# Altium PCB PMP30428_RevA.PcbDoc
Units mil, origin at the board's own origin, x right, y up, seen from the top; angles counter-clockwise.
Board outline 3031.5 x 2874.02 mil, 2 copper layers (Top Layer, Bottom Layer), stack 62 mil thick; 56 components, 35 nets, 134 pads, 10 vias.
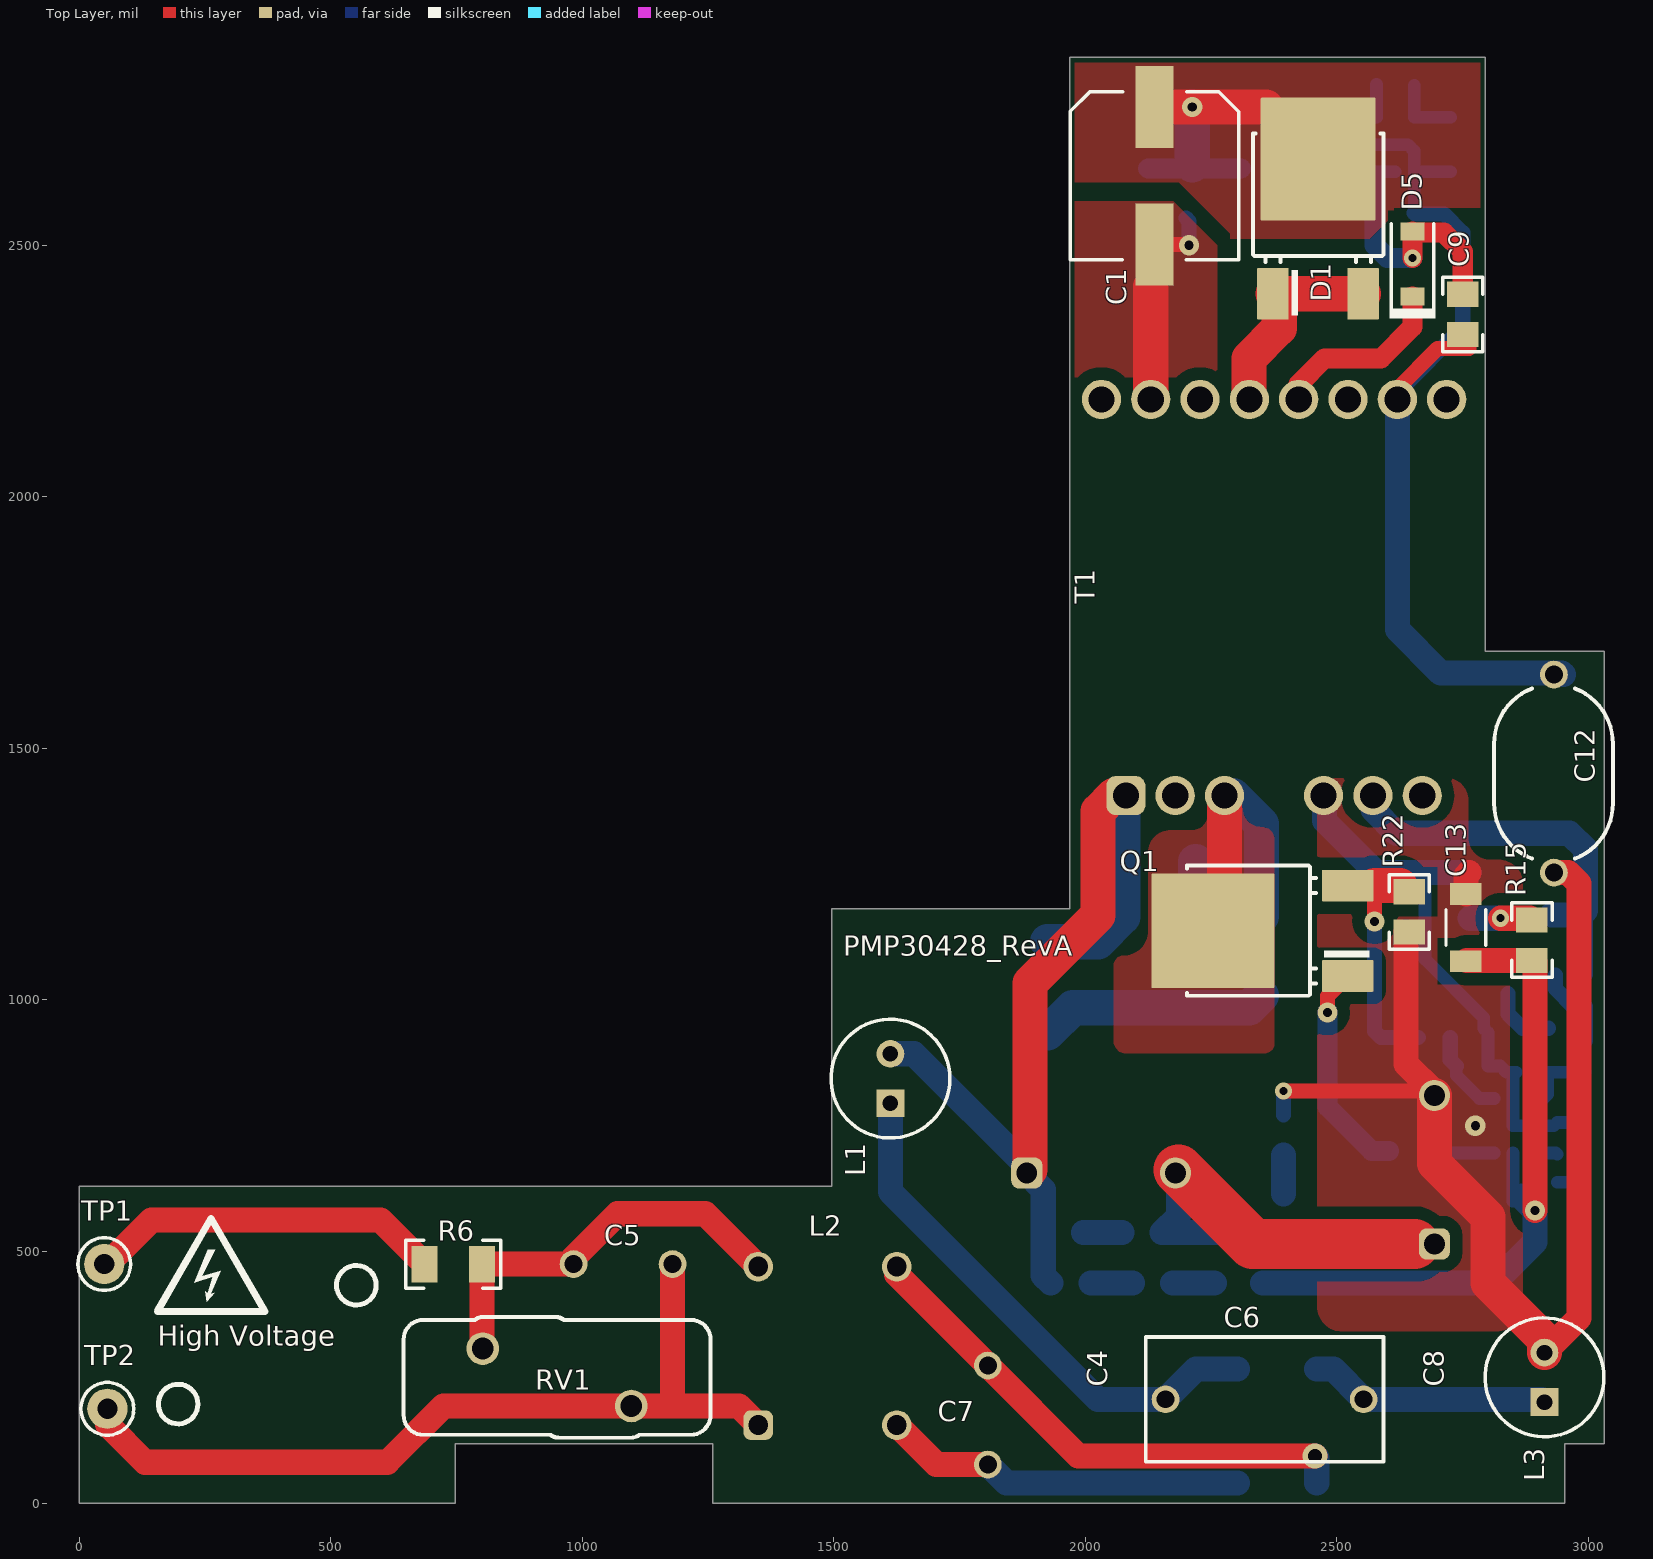
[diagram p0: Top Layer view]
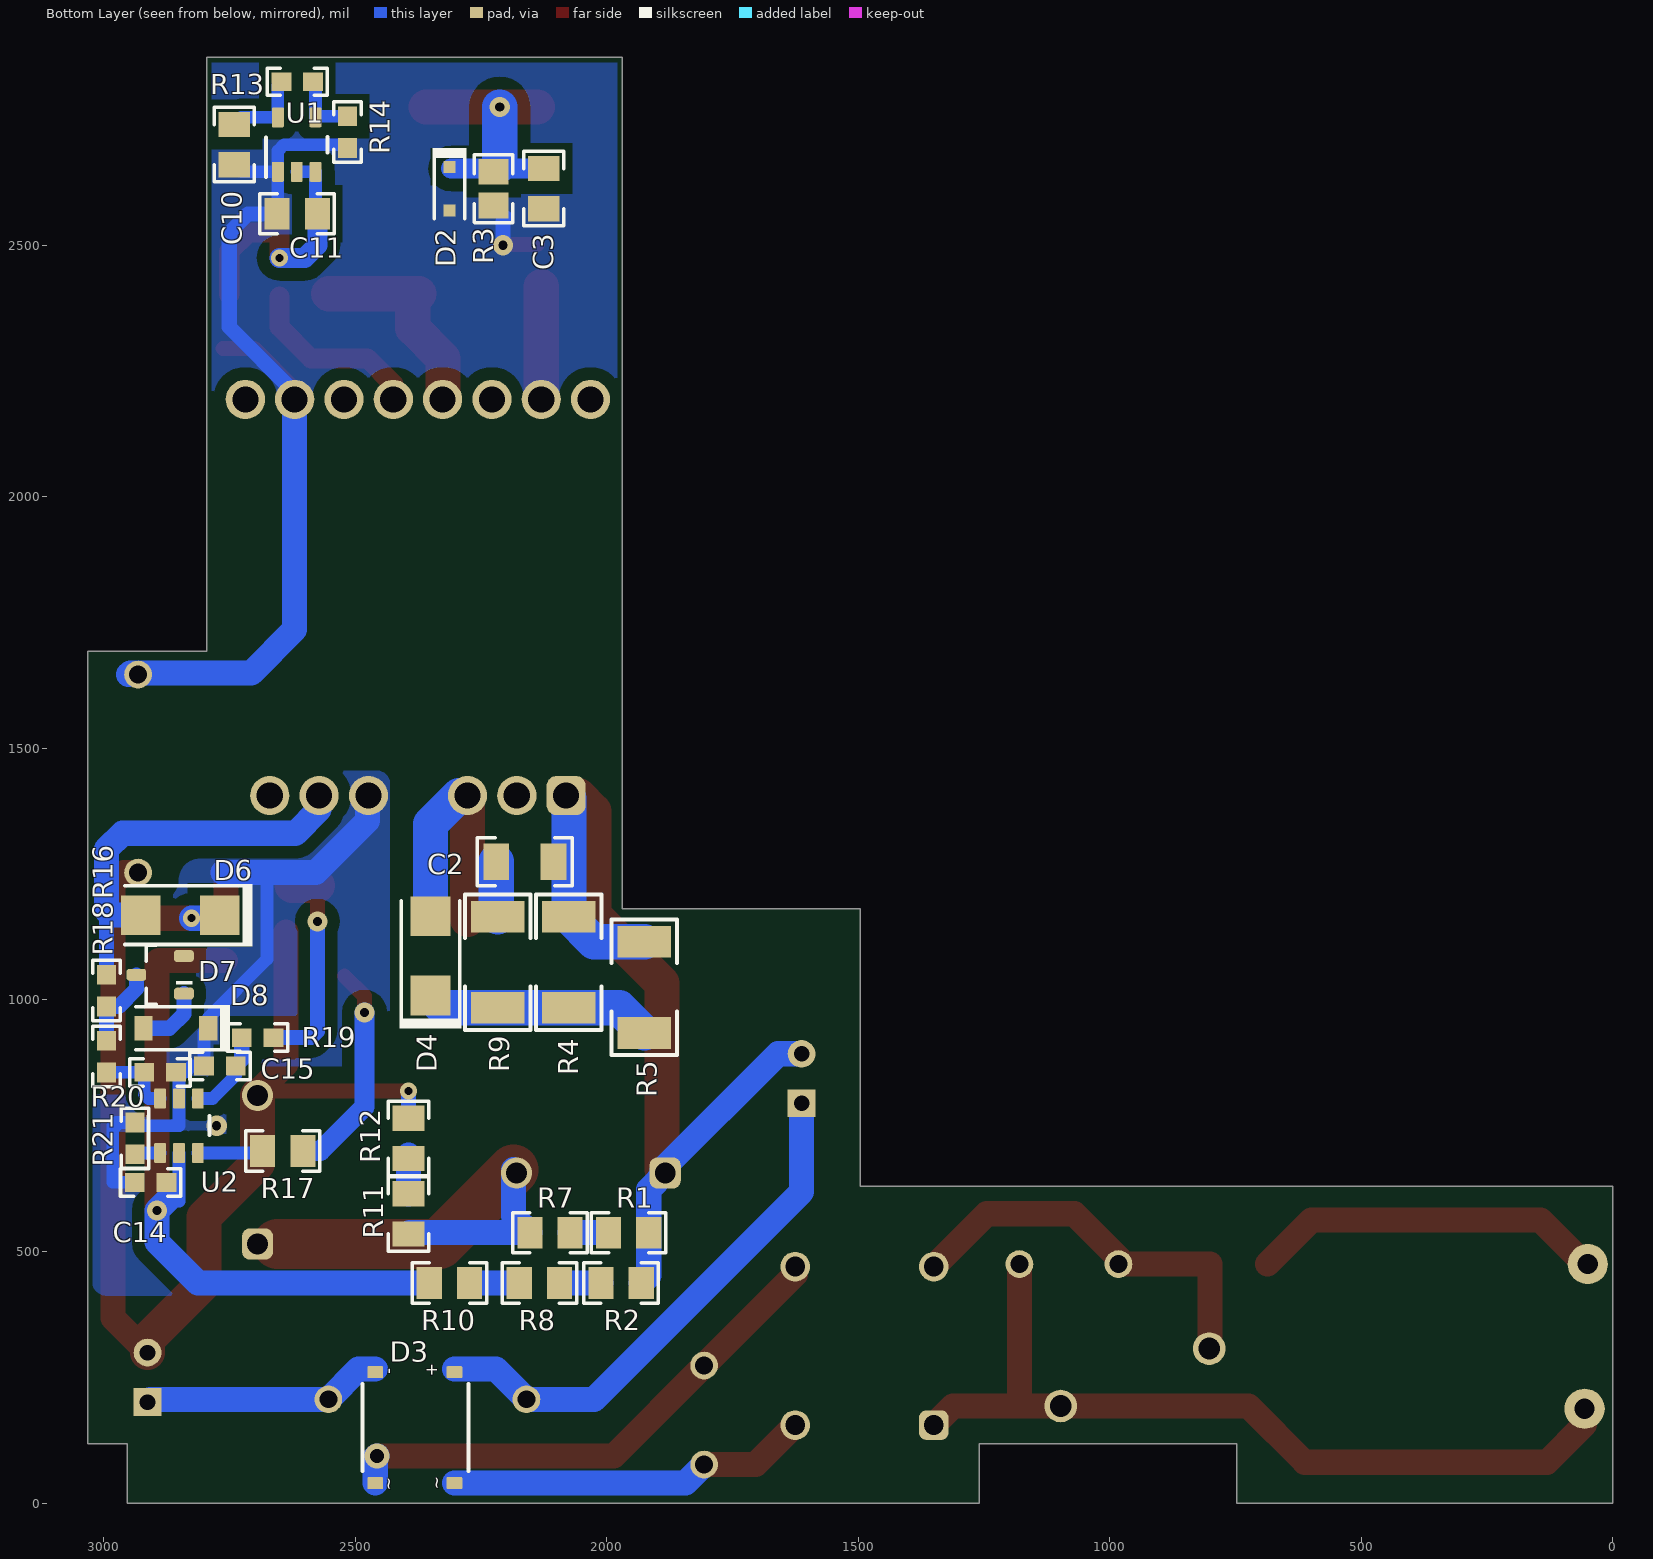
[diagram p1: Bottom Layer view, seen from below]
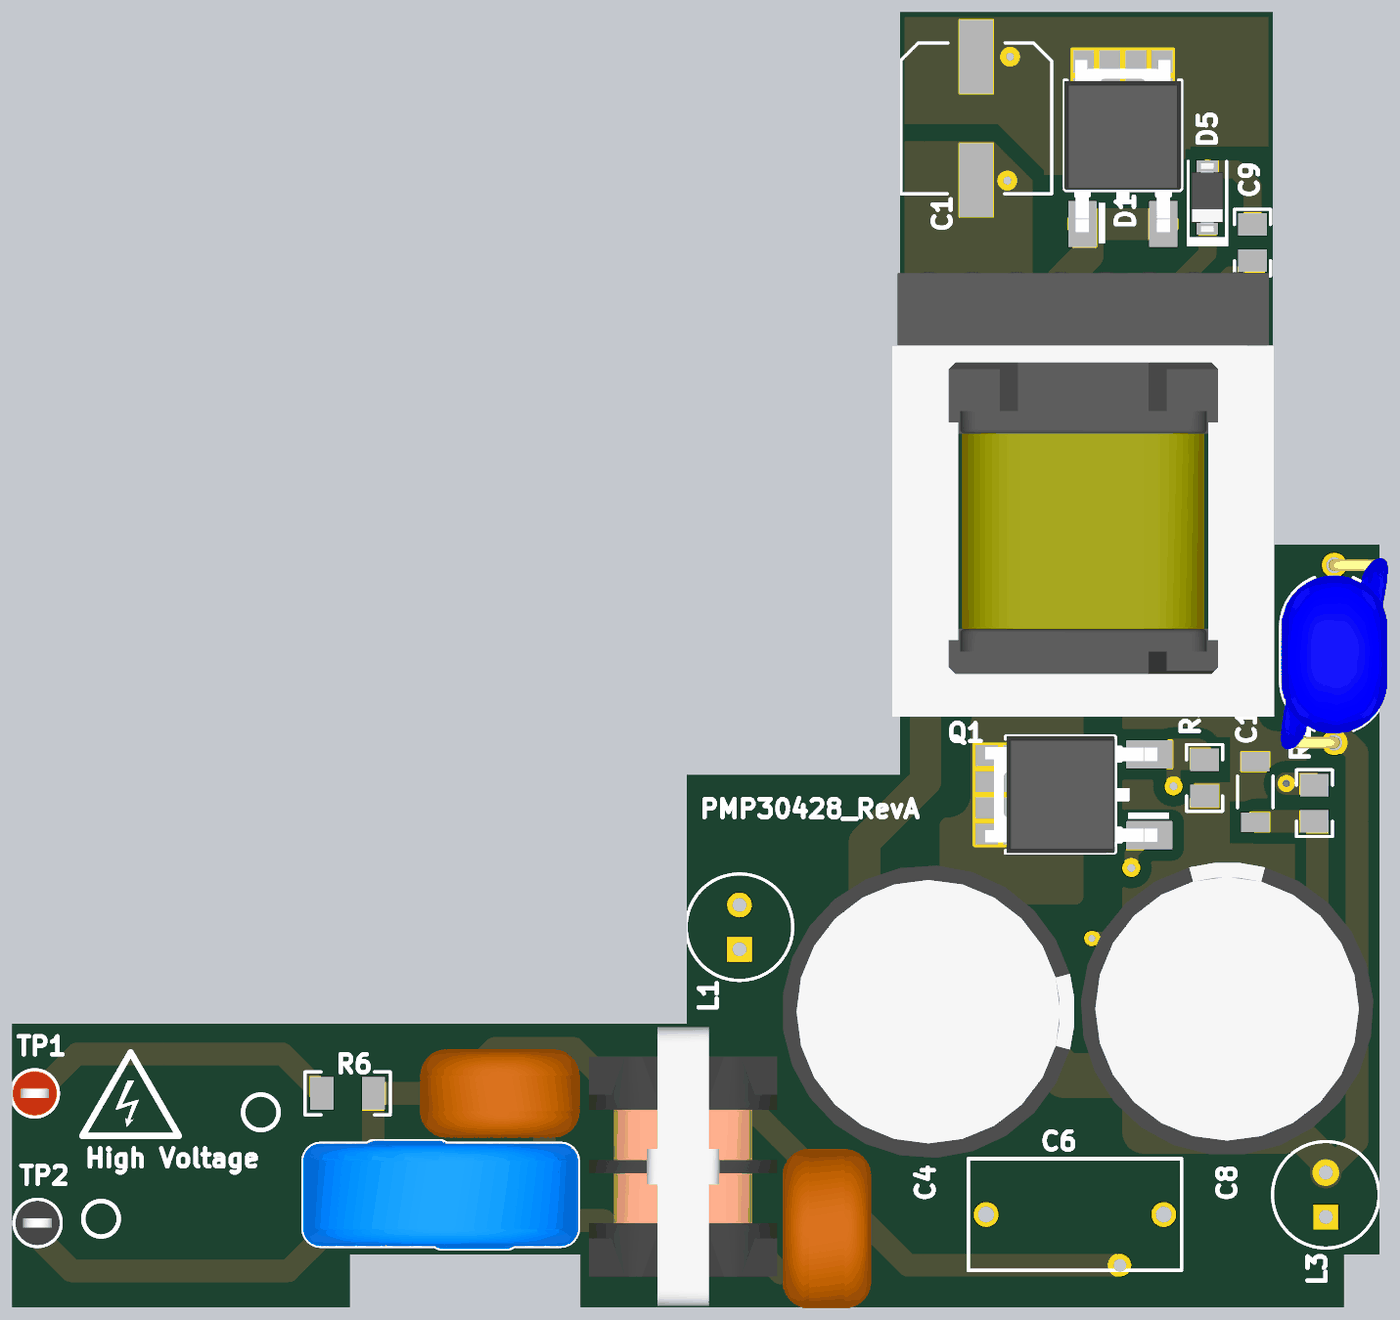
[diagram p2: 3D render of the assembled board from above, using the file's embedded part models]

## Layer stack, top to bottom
Top Solder: solder mask 0.4, Solder Resist, Dk 3.5
Top Layer: signal copper 1.4
Dielectric1: core 59.2, FR-4, Dk 4.8
Bottom Layer: signal copper 1.4
Bottom Solder: solder mask 0.4, Solder Resist, Dk 3.5

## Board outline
748.03,0 748.03,118.11 1259.84,118.11 1259.84,0 2952.76,0 2952.76,118.11 3031.5,118.11 3031.5,1692.91 2795.28,1692.91 2795.28,2874.02 1968.5,2874.02 1968.5,1181.1 1496.06,1181.1 1496.06,629.92 0,629.92 0,0

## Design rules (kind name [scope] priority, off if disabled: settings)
AcuteAngle [All] p1: minimum=4.50000000000000E+0001 checktracksonly=FALSE
AssemblyTestPointUsage [All] p1: valid=2
BoardOutlineClearance BoardOutlineClearance_MountingHoles [OnCopper and InComponentClass('Mounting Holes')] p1: gap=10 ignorepadtopadclearanceinfootprint=FALSE
BoardOutlineClearance BoardOutlineClearance_Poly [OnCopper and IsPoly] p2: gap=10 ignorepadtopadclearanceinfootprint=FALSE
BoardOutlineClearance [OnCopper and Not InComponentClass('Logo') and not InComponentClass('FiducialMark') and not InRegion(1000,500,4000,800) and not InPoly] p3: gap=10 ignorepadtopadclearanceinfootprint=FALSE
Clearance Clearance_Keepouts [((IsTrack Or IsArc) And Not InPoly) And IsFree and IsKeepOut vs ((IsTrack Or IsArc) And Not InPoly) And IsFree and IsKeepOut] p1: gap=0 ignorepadtopadclearanceinfootprint=FALSE
Clearance Clearance_Poly [InPolygon] p2: gap=25 ignorepadtopadclearanceinfootprint=FALSE except(0: Arc-Hole Track-Hole SMDPad-Hole THPad-Hole Via-Hole Fill-Hole Poly-Hole Region-Hole Text-Hole)
Clearance Clearance_FiducialMark [IsKeepOut and InComponentClass('FiducialMark') vs IsPad and InComponentClass('FiducialMark')] p3: gap=0 ignorepadtopadclearanceinfootprint=FALSE
Clearance [All] p4: gap=7.87 ignorepadtopadclearanceinfootprint=FALSE except(0: Arc-Hole Track-Hole SMDPad-Hole THPad-Hole Via-Hole Fill-Hole Poly-Hole Region-Hole Text-Hole)
ComponentClearance ComponentClearance_MountingHoles_FiducialMarks [InComponentClass('Mounting Holes') vs InComponentClass('FiducialMark')] p1: gap=10 collisioncheckmode=3 verticalgap=10 showdistances=FALSE
ComponentClearance ComponentClearance_Shunt [InComponentClass('Header') vs InComponentClass('Shunt')] p2: gap=0 collisioncheckmode=3 verticalgap=0 showdistances=FALSE
ComponentClearance ComponentClearance_Logo [InComponentClass('Logo')] p3: gap=20 collisioncheckmode=3 verticalgap=10 showdistances=FALSE
ComponentClearance ComponentClearance_ScrewToNut [(HasFootprint('NY PMS 440 0025 PH')) vs (HasFootprint('Keystone_1902C'))] p4: gap=5 collisioncheckmode=3 verticalgap=10 showdistances=FALSE
ComponentClearance ComponentClearance_MountingHoles [InComponentClass('Mounting Holes')] p5: gap=10 collisioncheckmode=3 verticalgap=100000 showdistances=FALSE
ComponentClearance ComponentClearance_SmallPassives [HasFootprint('0201*') or HasFootprint('0402*') or HasFootprint('0508') or HasFootprint('0603*') or HasFootprint('0612') or HasFootprint('0805*') or HasFootprint('0815*') or HasFootprint('0830*') or HasFootprint('1206*') or HasFootprint('1210*') or HasFootprint('1808*') or HasFootprint('1812*') or HasFootprint('1825*') or HasFootprint('2010*') or HasFootprint('2220*') or HasFootprint('2225*') or HasFootprint('2512*') or HasFootprint('2728*') or HasFootprint('3518*') vs HasFootprint('0201*') or HasFootprint('0402*') or HasFootprint('0508') or HasFootprint('0603*') or HasFootprint('0612') or HasFootprint('0805*') or HasFootprint('0815*') or HasFootprint('0830*') or HasFootprint('1206*') or HasFootprint('1210*') or HasFootprint('1808*') or HasFootprint('1812*') or HasFootprint('1825*') or HasFootprint('2010*') or HasFootprint('2220*') or HasFootprint('2225*') or HasFootprint('2512*') or HasFootprint('2728*') or HasFootprint('3518*')] p6: gap=10 collisioncheckmode=3 verticalgap=10 showdistances=FALSE
ComponentClearance ComponentClearance_THtoSMT [IsThruComponent vs IsSMTComponent] p7: gap=10 collisioncheckmode=3 verticalgap=10 showdistances=FALSE
ComponentClearance ComponentClearance_THtoTH [IsThruComponent vs IsThruComponent] p8: gap=10 collisioncheckmode=3 verticalgap=10 showdistances=FALSE
ComponentClearance [All] p9: gap=10 collisioncheckmode=3 verticalgap=10 showdistances=FALSE
DiffPairsRouting [All] p1: maxlimit=100 minlimit=10 mostfreqgap=10 toplayer_minwidth=15 toplayer_maxwidth=15 toplayer_prefwidth=15 bottomlayer_minwidth=15 bottomlayer_maxwidth=15 bottomlayer_prefwidth=15 maxuncoupledlength=1000
FabricationTestPointUsage TestPointUsage [All] p1: valid=2 allowmultiple=FALSE
FabricationTestpoint Testpoint [All] p1: side=3 testpointundercomponent=TRUE minsize=40 maxsize=100 preferedsize=60 minholesize=0 maxholesize=40 preferedholesize=32 testpointgrid=1 allowsidetop=TRUE allowsidebottom=TRUE usegrid=TRUE gridtolerance=0.01
FanoutControl Fanout_LCC [IsLCC] p1: bgadir=Out bgaviamode=Centered fanoutstyle=Auto fanoutdirection=Alternating viagrid=1 // Fanout_LCC (Default Rule)
FanoutControl Fanout_BGA [IsBGA] p2: bgadir=Out bgaviamode=Centered fanoutstyle=Auto fanoutdirection=Alternating viagrid=1 // Fanout_BGA (Default Rule)
FanoutControl Fanout_Default [All] p4: bgadir=Out bgaviamode=Centered fanoutstyle=Auto fanoutdirection=Alternating viagrid=1 // Fanout_Default (Default Rule)
FanoutControl Fanout_Small [(CompPinCount < 5)] p5: bgadir=Out bgaviamode=Centered fanoutstyle=Auto fanoutdirection=OutThenIn viagrid=1 // Fanout_Small (Default Rule)
Height [All] p1: minheight=0 maxheight=3000 prefheight=500
HoleSize [All] p1: absolutevalues=TRUE maxlimit=251 minlimit=7.87 maxpercent=80.000 minpercent=20.000
MinimumAnnularRing MinimumAnnularRing_ThermalPadVias [IsVia and InAnyComponent] p1: minimumring=5.91
MinimumAnnularRing [All] p2: minimumring=8
MinimumSolderMaskSliver MinimumSolderMaskSliver_Logo [InComponentClass('Logo') vs InComponentClass('Logo')] p1: minsoldermaskwidth=0.7
MinimumSolderMaskSliver [All] p2: minsoldermaskwidth=3.94
PlaneConnect [All] p1: planeconnectstyle=Direct reliefexpansion=10 reliefentries=4 reliefconductorwidth=10 reliefairgap=10
PolygonConnect [All] p1: connectstyle=Direct reliefconductorwidth=10 reliefentries=4 polygonreliefangle="90 Angle" airgapwidth=10
RoutingVias ThermalPadVias [IsVia and InAnyComponent] p1: holewidth=7.87 width=19.68 viastyle="Through Hole" minholewidth=7.87 minwidth=19.68 maxholewidth=12.99 maxwidth=23.62
RoutingVias [All] p2: holewidth=16 width=34 viastyle="Through Hole" minholewidth=7.87 minwidth=26 maxholewidth=40 maxwidth=65
SilkToBoardRegionClearance [Not ((IsComment or IsDesignator) And (Hide <> 'False')) and not InRegion(1000,500,4000,800)] p1:
SilkToSilkClearance SilkToSilkClearance_Pb-FreeLogo [(HasFootprint('Pb-Free_Overlay_Medium') OR HasFootprint('Pb-Free_Overlay_Small')) vs (HasFootprint('Pb-Free_Overlay_Medium') OR HasFootprint('Pb-Free_Overlay_Small'))] p1: silktosilkclearance=0
SilkToSilkClearance [All] p2: silktosilkclearance=0
SilkToSolderMaskClearance SilkToComponentPadClearance [(IsPad or IsFill or IsRegion) and InAnycomponent] p1: minsilkscreentomaskgap=0 clearancetoexposedcopper=TRUE
SilkToSolderMaskClearance "Silk to Solder Mask Opening" [All] p2: minsilkscreentomaskgap=0 clearancetoexposedcopper=FALSE
SolderMaskExpansion [All] p1: expansion=1.97
Width [All] p1: maxlimit=100 minlimit=6 preferedwidth=10 checkconnectedcopper=TRUE
14 further rules are at their usual default settings.

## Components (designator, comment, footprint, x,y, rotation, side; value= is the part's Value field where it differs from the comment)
C1 "16SVF560M" Panasonic_SMT_800x1190 2137.5,2638.09 r270 top value=560uF
C2 "GRM31BR72J152KW01L" 1206 2162.5,1275 r0 bottom value=1500pF
C3 "C0805C105K4RACTU" 0805_HV 2125,2612.5 r270 bottom value=1uF
C4 "UVZ2F470MHD" VZ_1600x2500 2031.25,656.25 r0 top value=47uF
C5 "VY2222M35Y5UG6TV5" VY2_900x500_5 1081.25,475 r0 top value=2200pF
C6 "ECQ-E4104JF" ECQE_F_1200x630x1200 2356.25,206.25 r0 top value=0.1uF
C7 "VY2222M35Y5UG6TV5" VY2_900x500_5 1806.25,175 r270 top value=2200pF
C8 "UVZ2F470MHD" VZ_1600x2500 2693.75,662.5 r90 top value=47uF
C9 "C0805C225K8RACTU" 0805_HV 2750,2362.5 r270 top value=2.2uF
C10 "C0805C225K8RACTU" 0805_HV 2740,2700 r270 bottom value=2.2uF
C11 "GRM219R71C104KA01D" 0805_HV 2615,2562.5 r0 bottom value=0.1uF
C12 "CD45-E2GA222M-NKA" CD45_900x600x1300 2931.25,1450 r270 top value=2200pF
C13 "C3216X7R1H335K160AC" 1206_190 2756.25,1143.75 r90 top value=3.3uF
C14 "GRM188R71H104KA93D" 0603 2906.25,637.5 r0 bottom value=0.1uF
C15 "Used in BOM report" 0603 2768.75,868.75 r0 bottom value=DNP
D1 "MBRD5150" DPAK 2462.5,2537.5 r90 top value=150V
D2 "MMSZ5245BS-7-F" SOD-323 2312.5,2612.5 r270 bottom value=15V
D3 "ABS10-G" ABS 2381.25,150 r270 bottom value=1000V
D4 "US1J-13-F" SMA 2350,1087.5 r90 bottom value=600V
D5 "MBR0560-TP" SOD-123 2650,2462.5 r90 top value=60V
D6 "ES1F" SMA 2847.5,1168.75 r0 bottom value=300V
D7 "BAS21-7-F" SOT-23 2887.5,1050 r0 bottom value=200V
D8 "MMSZ5250B-7-F" SOD-123 2856.25,943.75 r0 bottom value=20V
"High Voltage" "DANGER HIGH VOLTAGE" IEC_HighVoltage_Small 262.5,468.75 r0 top
L1 "7447462221" WE-TI_5075 1612.5,843.75 r90 top value=220uH
L2 "744862100" Wurth_WE-TFC_UT 1487.5,312.5 r90 top value=10mH
L3 "7447462221" WE-TI_5075 2912.5,250 r90 top value=220uH
Q1 "STD4N80K5" DPAK 2387.5,1137.5 r180 top value=800V
R1 "CRCW08051M00JNEA" 0805_HV 1956.25,537.5 r180 bottom value=1.0Meg
R2 "CRCW08052M00JNEA" 0805_HV 1971.25,437.5 r180 bottom value=2.0Meg
R3 "Used in BOM report" 0805 2225,2612.5 r90 bottom value=DNP
R4 "CRCW2010100KFKEF" 2010 2075,1075 r90 bottom value=100k
R5 "Used in BOM report" 2010 1925,1025 r90 bottom value=DNP
R6 "Used in BOM report" 1206 743.75,475 r180 top
R7 "CRCW08051M00JNEA" 0805_HV 2112.5,537.5 r180 bottom value=1.0Meg
R8 "CRCW08052M00JNEA" 0805_HV 2133.75,437.5 r180 bottom value=2.0Meg
R9 "CRCW2010100RJNEF" 2010 2216.31,1075 r90 bottom value=100
R10 "CRCW08052M00JNEA" 0805_HV 2312.5,437.5 r180 bottom value=2.0Meg
R11 "CRCW08051M00JNEA" 0805_HV 2393.75,575 r270 bottom value=1.0Meg
R12 "CRCW08051M00JNEA" 0805_HV 2393.75,725 r270 bottom value=1.0Meg
R13 "CRCW060363R4FKEA" 0603 2615,2825 r0 bottom value=63.4
R14 "CRCW060336K5FKEA" 0603 2515,2725 r90 bottom value=36.5k
R15 "CRCW080522R0JNEA" 0805_HV 2887.5,1118.75 r90 top value=22
R16 "CRCW0603130KFKEA" 0603 2993.75,1018.75 r90 bottom value=130k
R17 "CRCW08050000Z0EA" 0805_HV 2643.75,700 r180 bottom value=0
R18 "CRCW060320K0FKEA" 0603 2993.75,887.5 r270 bottom value=20.0k
R19 "CRCW06031K21FKEA" 0603 2693.75,925 r180 bottom value=1.21k
R20 "CRCW060328K7FKEA" 0603 2887.5,856.25 r0 bottom value=28.7k
R21 "CRCW0603100KFKEA" 0603 2937.5,725 r270 bottom value=100k
R22 "ERJ-6RQF1R0V" 0805_HV 2643.75,1175 r90 top value=1.00
RV1 "B72214S0421K331" TDK_B72214S0421 950,250 r180 top
T1 "750317406" Wurth_750317406 2375,1800 r90 top value=600uH
TP1 "5000" Keystone5000 50,475 r90 top
TP2 "5001" Keystone5001 56.25,187.5 r90 top
U1 "TPS72301DBVR" DBV0005A_N 2616.03,2700 r90 bottom
U2 "UCC28700DBVR" DBV0006A_N 2850,750 r90 bottom

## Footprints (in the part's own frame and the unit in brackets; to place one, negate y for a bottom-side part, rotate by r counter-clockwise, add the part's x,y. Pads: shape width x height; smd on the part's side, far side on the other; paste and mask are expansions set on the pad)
0603 [mm] "0603 from SM-752 data"
  rect 1x0.95 smd: 1(-0.8,0) 2(0.8,0)
  silkscreen extent -1.52,-0.69 1.52,0.69, body extent -0.87,-0.47 0.87,0.47, height 1
0805 [mm] "0805 from SM-752 data"
  rect 1.3x1.5 smd: 1(-0.85,0) 2(0.85,0)
  silkscreen extent -1.72,-0.97 1.72,0.97, body extent -1.1,-0.72 1.1,0.72, height 1.45
0805_HV [mil] "0805 with 30mil clearance between pads"
  rect 50x63 smd: 1(-40,0) 2(40,0)
  silkscreen extent -74,-40 74,40, body extent -43,-29 43,29, height 57
1206 [mm] "1206 from SM-752 data"
  rect 1.3x1.85 smd: 1(-1.45,0) 2(1.45,0)
  silkscreen extent -2.4,-1.21 2.4,1.21, body extent -1.7,-0.9 1.7,0.9, height 1.35
1206_190 [mm] "1206_190"
  rect 1.1x1.6 smd: 1(-1.7,0) 2(1.7,0)
  silkscreen extent -0.9,-1 0.9,1, body extent -1.75,-0.95 1.75,0.95, height 1.9
2010 [mm] "Chip Capacitor, Body 5.08x2.54mm, IPC Medium Density"
  rect 1.6x2.7 smd: 1(-2.3,0) 2(2.3,0)
  silkscreen extent -3.42,-1.65 3.42,1.65, body extent -2.73,-1.45 2.73,1.45, height 1.66
ABS [mm] "Comchip"
  rrect17% 0.6x0.8 smd: 1(-2.8,2) 2(2.8,2) 3(2.8,-2) 4(-2.8,-2)
  silkscreen extent -2.2,-2.65 2.2,2.7, body extent -3.2,-2.6 3.2,2.6, height 1.5
CD45_900x600x1300 [mm] "TH, 2-Leads, Dia 9mm, Pin Spacing 10 mm"
  round 1.4 hole 0.9: 1(-5,0) 2(5,0)
  silkscreen extent -4.29,-3.02 4.3,2.98, body extent -5.39,-3.01 5.39,3.01, height 13
DBV0005A_N [mm] "SOT23, 5-Leads, Body 2.9x1.6mm, Pitch 0.95mm, Lead Span 2.8mm, IPC Medium Density"
  rrect17% 1x0.6 smd: 1(-1.375,0.95) 2(-1.375,0) 3(-1.375,-0.95) 4(1.375,-0.95) 5(1.375,0.95)
  silkscreen extent -1.63,-1.55 0.38,1.55, body extent -1.42,-1.46 1.42,1.46, height 1.09
DBV0006A_N [mm] "SOT23, 6-Leads, Body 2.9x1.6mm, Pitch 0.95mm, Lead Span 2.8mm, IPC Medium Density"
  rrect17% 1x0.6 smd: 1(-1.375,0.95) 2(-1.375,0) 3(-1.375,-0.95) 4(1.375,-0.95) 5(1.375,0) 6(1.375,0.95)
  silkscreen extent -1.68,-1.55 0.5,1.55, body extent -1.42,-1.46 1.42,1.46, height 1.12
DPAK [mm] "D-PAK, 3-Pads, Body 6.22x6.73mm (max), TO-252AA using nominal STEP model"
  rrect6% 2.6x1.6 smd: 1(-3.4,2.28) 3(-3.4,-2.28)
  rrect2% 6.2x5.8 smd paste-2.9: 4(3.4,0)
  silkscreen extent -4.5,-3.3 4.7,3.28, body extent -3.86,-3.29 5.84,3.29, height 2.48
ECQE_F_1200x630x1200 [mm] "TH, 2-Leads, Body 12x6.3mm, Lead Spacing 10mm"
  round 1.4 hole 0.9: 1(-5,0) 2(5,0)
  silkscreen extent -6,-3.15 6,3.15, body extent -6,-3.15 6,3.15, height 12
IEC_HighVoltage_Small [mil]
  silkscreen extent -107,-88 107,97
Keystone5000 [mil] "For Keystone 500x miniature loop terminals"
  round 80 hole 40: 1(0,0)
  silkscreen extent -52,-52 52,52, body extent -49,-49 49,49, height 182
Keystone5001 [mil] "For Keystone 500x miniature loop terminals"
  round 80 hole 40: 1(0,0)
  silkscreen extent -52,-52 52,52, body extent -49,-49 49,49, height 182
Panasonic_SMT_800x1190 [mm] "SMD, 2-Leads, Body 8.3x8.3mm"
  rect 4.15x1.9 smd: 1(-3.475,0) 2(3.475,0)
  silkscreen extent -4.25,-4.25 4.25,4.25, body extent -4.25,-4.25 4.25,4.25, height 12
SMA [mm] "Molded Diode, 2-Leads, Body 4.3x2.6mm, IPC Medium Density, based on OnSemi component dimensions and land pattern"
  rect 2x2 smd: 1(-2,0) 2(2,0)
  silkscreen extent -3.66,-1.57 2.79,1.57, body extent -2.6,-1.3 2.6,1.3, height 2.42
SOD-123 [mm] "On Semi recommended land pattern"
  rect 0.915x1.22 smd: 1(-1.637,0) 2(1.637,0)
  silkscreen extent -2.74,-1.17 2.03,1.17, body extent -1.93,-0.9 1.93,0.9, height 1.35
SOD-323 [mm] "NXP recommended land pattern"
  rect 0.6x0.6 smd paste-0.05: 1(-1.1,0) 2(1.1,0)
  silkscreen extent -2.06,-0.86 1.53,0.86, body extent -1.3,-0.67 1.3,0.68, height 1.1
SOT-23 [mm] "SOT23, 3-Leads, Body 2.9x1.3mm, Pitch 0.95mm, Lead Span 2.5mm, IPC Medium Density"
  rrect50% 1x0.6 smd: 1(-1.2,0.95) 2(-1.2,-0.95) 3(1.2,0)
  silkscreen extent -1.63,-1.5 0.7,1.5, body extent -1.16,-1.45 1.21,1.45, height 1
TDK_B72214S0421 [mm] "TH, 2-Leads, Body 15.5x6.1mm, Pin Spacing 7.5mm"
  round 1.65 hole 1.1: 1(-3.75,1.45) 2(3.75,-1.45)
  silkscreen extent -7.75,-3.05 7.75,3.05, body extent -7.75,-3.05 7.75,3.05, height 18.5
VY2_900x500_5 [mm] "TH, 2-Leads, Body 9x5mm, Lead Spacing 5mm"
  round 1.4 hole 0.9: 1(-2.5,0) 2(2.5,0)
  body extent -4.5,-2.5 4.5,2.5, height 13
VZ_1600x2500 [mm] "TH, 2-Leads, Dia 16mm, Pin Spacing 7.5mm"
  rrect50% 1.575x1.575 hole 1.05: 1(-3.75,0)
  round 1.575 hole 1.05: 2(3.75,0)
  body extent -8.25,-8.25 8.26,8.25, height 27.01
WE-TI_5075 [mm] "Wurth WE-TI 5075"
  rect 1.4x1.4 hole 0.787: 1(-1.25,0)
  round 1.4 hole 0.787: 2(1.25,0)
  silkscreen extent -3,-3 3,3, body extent -3,-3 3,3, height 8.5
Wurth_750317406 [mm] "TH, 14-Leads, Body 25x21.5mm"
  rrect50% 1.98x1.98 hole 1.32: 1(-10,7.48)
  round 1.98 hole 1.32: 2(-10,4.99) 3(-10,2.5) 4(-10,-2.5) 5(-10,-4.99) 6(-10,-7.48) 7(10,-8.715) 8(10,-6.225) 9(10,-3.735) 10(10,-1.245) 11(10,1.245) 12(10,3.735) 13(10,6.225) 14(10,8.715)
  body extent -12.43,-10.74 12.65,10.76, height 15.4
Wurth_WE-TFC_UT [mm] "TH, 4-Leads, Body 11x17mm"
  rrect50% 1.5x1.5 hole 1: 1(-4,3.5)
  round 1.5 hole 1: 2(-4,-3.5) 3(4,-3.5) 4(4,3.5)
  body extent -7.85,-5.3 7.85,5.3, height 15.75

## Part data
C1: library part CMP-0081113-1, "CAP, Aluminum Polymer, 560 µF, 16 V,+/- 20%, 0.014 ohm, 8x11.9 SMD", Cap_Case=0.8x11.9mm, Manufacturer=Panasonic, Supplier Part Number 1=P122113CT-ND, Tolerance_%=20%, Value1="0.014 ohm", Value2=16V, ValueDisplayed=560µF
C2: "CAP, CERM, 1500 pF, 630 V,+/- 10%, X7R, 1206", Cap_Case=1206, Manufacturer=MuRata, Supplier Part Number 1=490-3507-1-ND, TempCo=X7R, Tolerance_%=10, Value2=630V, ValueDisplayed=1500pF
C3: "CAP, CERM, 1 µF, 16 V,+/- 10%, X7R, 0805", Cap_Case=0805, Manufacturer=Kemet, Supplier Part Number 1=399-1284-1-ND, TempCo=X7R, Tolerance_%=10, Value1="0.015 ohm", Value2=16V, ValueDisplayed=1µF
C4 C8: library part CMP-0081190-1, "CAP, AL, 47 µF, 315 V, +/- 20%, TH", Cap_Case=16x25mm, Manufacturer=Nichicon, Supplier Part Number 1=493-1430-ND, Tolerance_%=20%, Value2=315V, ValueDisplayed=47µF
C5 C7: library part CMP-0080613-1, "CAP, CERM, 2200 pF, X1 440 VAC/Y2 300 VAC, +/- 20%, Y5U, Body9x5mm", Cap_Case=9x5mm, Manufacturer=Vishay-Bccomponents, TempCo=Y5U, Tolerance_%=20%, ValueDisplayed=2200pF
C6: library part CMP-0064980-3, "CAP, Film, 0.1 uF, 400 V,+/- 5%, TH", Cap_Case=12x6.3x12mm, Manufacturer=Panasonic, Supplier Part Number 1=P14568-ND, Tolerance_%=5%, Value1=Unknown, Value2=400V, ValueDisplayed=0.1uF
C9 C10: "CAP, CERM, 2.2 µF, 10 V,+/- 10%, X7R, 0805", Cap_Case=0805, Manufacturer=Kemet, Supplier Part Number 1=399-3522-1-ND, TempCo=X7R, Tolerance_%=10, Value1="0.008 ohm", Value2=10V, ValueDisplayed=2.2µF
C11: "CAP, CERM, 0.1 µF, 16 V,+/- 10%, X7R, 0805", Cap_Case=0805, Manufacturer=MuRata, Supplier Part Number 1=490-1683-1-ND, TempCo=X7R, Tolerance_%=10, Value2=16V, ValueDisplayed=0.1µF
C12: "CAP, CERM, 2200 pF, X1 440 VAC/Y1 400 VAC, +/- 20%, E, D9xT6mm", Cap_Case=9x6x13mm, Manufacturer=TDK, Supplier Part Number 1=445-174537-ND, TempCo=E, Tolerance_%=20, ValueDisplayed=2200pF
C13: "CAP, CERM, 3.3 µF, 50 V,+/- 10%, X7R, 1206", Cap_Case=1206, Manufacturer=TDK, Supplier Part Number 1=445-5990-1-ND, TempCo=X7R, Tolerance_%=10, Value2=50V, ValueDisplayed=3.3µF
C14: "CAP, CERM, 0.1 µF, 50 V,+/- 10%, X7R, 0603", Cap_Case=0603, Manufacturer=MuRata, Supplier Part Number 1=490-1519-1-ND, TempCo=X7R, Tolerance_%=10, Value2=50V, ValueDisplayed=0.1µF
C15: library part Capacitor, "CAP, CERM, xxxF, xxV, [TempCo], xx%, [PackageReference]", Alternate Manufacturer=-
D1: library part MBRD360T4G, "Diode, Schottky, 150V, DPAK", Capacitance @ Vr, F="150pF @ 5V, 1MHz", Manufacturer="ON Semiconductor", Operating Temperature - Junction="-55°C ~ 150°C", Supplier Device Package=DPAK, Value2=0.6V
D2: "Diode, Zener, 15 V, 200 mW, SOD-323", Manufacturer="Diodes Inc.", Power_W=0.2, Supplier Part Number 1=MMSZ5245BS-FDICT-ND, Value1=0.2W
D3: "Diode, Switching-Bridge, 1000 V, 1 A, 6.2x5.0mm", Manufacturer="Comchip Technology", Supplier Part Number 1=ABS10-G-ND, Value1=1A, Value2=1.1V
D4: "Diode, Ultrafast, 600 V, 1 A, SMA", Manufacturer="Diodes Inc.", Supplier Part Number 1=US1J-FDICT-ND, Value1=1A, Value2=1.7V
D5: "Diode, Schottky, 60 V, 3 A, SOD-123", Manufacturer="Micro Commercial Components", Supplier Part Number 1=MBR0560TPMSCT-ND, Value1=3A, Value2=0.45V
D6: library part ES1G-13-F, "Diode, Superfast Rectifier, 400 V, 1 A, SMA", Average Rectified Current=1A, Case/Package=SMA, Forward Voltage=1.3V, Manufacturer="Diodes Inc.", Max Forward Surge Current (Ifsm)=30A, Max Operating Temperature=150°C, Max Repetitive Reverse Voltage (Vrrm)=300V, Min Operating Temperature=-55°C, Package Quantity=1, Peak Reverse Current=5uA, Value2=1.25V
D7: "Diode, Switching, 200 V, 0.2 A, SOT-23", Manufacturer="Diodes Inc.", Supplier Part Number 1=BAS21-FDICT-ND, Value1=0.2A, Value2=1.25V
D8: "Diode, Zener, 20 V, 500 mW, SOD-123", Manufacturer="Diodes Inc.", Power_W=0.5, Supplier Part Number 1=MMSZ5250B-FDICT-ND, Value1=0.5W
"High Voltage": library part IEC_HighVoltage, "IEC 61010-1 High Voltage Warning"
L1 L3: library part CMP-0064740-2, "Inductor, Unshielded Drum Core, Ferrite, 220 uH, 0.5 A, 0.96 ohm, TH", Manufacturer="Wurth Elektronik", Supplier Part Number 1=732-2574-ND, Value1="0.96 ohm", Value2=0.5A, ValueDisplayed=220uH
L2: library part CMP-0080644-1, "Coupled inductor, 10 mH, 1.65 ohm, TH", Manufacturer="Wurth Elektronik", Supplier Part Number 1=732-7193-ND, ValueDisplayed=10mH
Q1: library part STD3NK80ZT4, "MOSFET, N-CH, 800 V, DPAK", Alternate Manufacturer=None, Case/Package=DPAK, Continuous Drain Current (ID)=3A, Drain to Source Breakdown Voltage=800V, Drain to Source Resistance=2.1R, Gate to Source Voltage (Vgs)=30V, Input Capacitance=175pF, Manufacturer=STMicroelectronics, Max Operating Temperature=150°C, Max Power Dissipation=60W, Min Operating Temperature=-55°C, Package Quantity=1, Value1="? ohm", Value2="19 nC"
R1 R7 R11 R12: "RES, 1.0 M, 5%, 0.125 W, 0805", Manufacturer=Vishay-Dale, Power_W=0.125, Supplier Part Number 1=541-1.0MACT-ND, TempCo="200 ppm/C", Tolerance_%=5, Value1=5%, Value2=0.125W, Value_Code=1M00, ValueDisplayed=1.0M
R2 R8 R10: "RES, 2.0 M, 5%, 0.125 W, 0805", Manufacturer=Vishay-Dale, Power_W=0.125, Supplier Part Number 1=541-2.0MACT-ND, TempCo="200 ppm/C", Tolerance_%=5, Value1=5%, Value2=0.125W, Value_Code=2M00, ValueDisplayed=2.0M
R3 R5 R6: library part Resistor, "RES, xxx ohm, x%, xW, [PackageReference]", Alternate Manufacturer=-
R4: "RES, 100 k, 1%, 0.75 W, AEC-Q200 Grade 0, 2010", Manufacturer=Vishay-Dale, Power_W=0.75, Supplier Part Number 1=541-100KACCT-ND, TempCo="100 ppm/C", Tolerance_%=1, Value1=1%, Value2=0.75W, Value_Code=100k
R9: "RES, 100, 5%, 0.75 W, AEC-Q200 Grade 0, 2010", Manufacturer=Vishay-Dale, Power_W=0.75, Supplier Part Number 1=541-100WCT-ND, TempCo="200 ppm/C", Tolerance_%=5, Value1=5%, Value2=0.75W, Value_Code=100R, ValueDisplayed=100
R13: "RES, 63.4, 1%, 0.1 W, 0603", Manufacturer=Vishay-Dale, Power_W=0.1, Supplier Part Number 1=541-63.4HCT-ND, TempCo="100 ppm/C", Tolerance_%=1, Value1=1%, Value2=0.1W, Value_Code=63R4, ValueDisplayed=63.4
R14: "RES, 36.5 k, 1%, 0.1 W, 0603", Manufacturer=Vishay-Dale, Power_W=0.1, Supplier Part Number 1=541-36.5KHCT-ND, TempCo="100 ppm/C", Tolerance_%=1, Value1=1%, Value2=0.1W, Value_Code=36k5, ValueDisplayed=36.5k
R15: "RES, 22, 5%, 0.125 W, 0805", Manufacturer=Vishay-Dale, Power_W=0.125, Supplier Part Number 1=541-22ACT-ND, TempCo="200 ppm/C", Tolerance_%=5, Value1=5%, Value2=0.125W, Value_Code=22R0, ValueDisplayed=22
R16: "RES, 130 k, 1%, 0.1 W, 0603", Manufacturer=Vishay-Dale, Power_W=0.1, Supplier Part Number 1=541-130KHCT-ND, TempCo="100 ppm/C", Tolerance_%=1, Value1=1%, Value2=0.1W, Value_Code=130k
R17: "RES, 0, 5%, 0.125 W, 0805", Manufacturer=Vishay-Dale, Power_W=0.125, Supplier Part Number 1=541-0.0ACT-ND, TempCo="200 ppm/C", Tolerance_%=5, Value1=5%, Value2=0.125W, Value_Code=0000, ValueDisplayed=0
R18: "RES, 20.0 k, 1%, 0.1 W, 0603", Manufacturer=Vishay-Dale, Power_W=0.1, Supplier Part Number 1=541-20.0KHCT-ND, TempCo="100 ppm/C", Tolerance_%=1, Value1=1%, Value2=0.1W, Value_Code=20k0, ValueDisplayed=20.0k
R19: "RES, 1.21 k, 1%, 0.1 W, 0603", Manufacturer=Vishay-Dale, Power_W=0.1, Supplier Part Number 1=541-1.21KHCT-ND, TempCo="100 ppm/C", Tolerance_%=1, Value1=1%, Value2=0.1W, Value_Code=1k21, ValueDisplayed=1.21k
R20: "RES, 28.7 k, 1%, 0.1 W, 0603", Manufacturer=Vishay-Dale, Power_W=0.1, Supplier Part Number 1=541-28.7KHCT-ND, TempCo="100 ppm/C", Tolerance_%=1, Value1=1%, Value2=0.1W, Value_Code=28k7, ValueDisplayed=28.7k
R21: "RES, 100 k, 1%, 0.1 W, 0603", Manufacturer=Vishay-Dale, Power_W=0.1, Supplier Part Number 1=541-100KHCT-ND, TempCo="100 ppm/C", Tolerance_%=1, Value1=1%, Value2=0.1W, Value_Code=100k
R22: "RES, 1.00, 1%, 0.125 W, 0805", Manufacturer=Panasonic, Power_W=0.125, Supplier Part Number 1=P1.0DCT-ND, TempCo="200 ppm/C", Tolerance_%=1, Value1=1%, Value2=0.125W, Value_Code=1R00, ValueDisplayed=1.00
RV1: library part CMP-0080633-1, "VARISTOR", Manufacturer=TDK, PartNumber=S14K420, Supplier Part Number 1=495-6533-1-ND
T1: library part CMP-0080922-1, "Transformer, 600 uH, TH", Manufacturer="Wurth Elektronik", ValueDisplayed=600µH
TP1: "Test Point, Miniature, Red, TH", Color=Red, Manufacturer=Keystone, Supplier Part Number 1=36-5000-ND
TP2: "Test Point, Miniature, Black, TH", Color=Black, Manufacturer=Keystone, Supplier Part Number 1=36-5001-ND
U1: "Single Output LDO, 200 mA, Adjustable -10 to -1.2 V Output, -10 to -2.7 V Input, 5-pin SOT-23 (DBV), -40 to 125 degC, Green (RoHS & no Sb/Br)", Alternate Manufacturer="Texas Instruments", Alternate PartNumber=Equivalent, Supplier Part Number 1=296-27049-2-ND
U2: "Constant-Voltage, Constant-Current PWM With Primary-Side Regulation, DBV0006A (SOT-23-6)", Alternate Manufacturer="Texas Instruments", Alternate PartNumber=UCC28700DBVT

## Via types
v1: diameter 40, hole 18, Top Layer to Bottom Layer, 6 vias
v2: diameter 34, hole 16, Top Layer to Bottom Layer, 3 vias
v3: diameter 50, hole 28, Top Layer to Bottom Layer, 1 vias

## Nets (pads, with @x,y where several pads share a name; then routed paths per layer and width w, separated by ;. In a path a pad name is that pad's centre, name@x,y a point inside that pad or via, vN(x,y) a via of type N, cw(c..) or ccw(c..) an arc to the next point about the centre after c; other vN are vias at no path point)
GND: C1.2 C3.2 C9.2 C10.2 C11.2 C12.1 D2.2 R3.1 R14.1 T1.8 T1.13 U1.1 | length 2211.4
  Top Layer w30: C1.2 2198.72,2501.28 2200,2500 v1(2206.25,2500) ; T1.8 2620.08,2214.77 2700,2294.69 2762.5,2294.69
  Top Layer w70: T1.13 2129.92,2418.11
  Bottom Layer w25: R14.1 2521.5,2700 2641.03,2700 2653.43,2687.6 U1.1 ; C11.2@2653.43,2564.07 U1.1 ; C10.2@2725.87,2645.87 U1.1
  Bottom Layer w30: R3.1@2200,2554.04 2206.25,2547.79 v1(2206.25,2500) ; T1.8 2620.08,2207.58 2750,2337.5 2750,2525 2712.5,2562.5 C11.2 C11.2@2653.43,2564.07
  Bottom Layer w50: T1.8 2620.08,1736.17 2706.25,1650 2946.85,1650 C12.1@2950,1646.85
NetC1_1: C1.1 C3.1 D1.4 D2.1 R3.2 | length 520.6
  Top Layer w70: C1.1 v1(2212.5,2774.9) D1.4@2358.96,2774.9
  Bottom Layer w40: C3.1 D2.1@2309.19,2652.5
  Bottom Layer w70: R3.2@2212.5,2660 v1(2212.5,2774.9)
NetC2_1: C2.1 C4.1 L1.2 R1.2 R2.2 R4.2 R5.2 T1.1 | length 1862
  Top Layer w70: C4.1@1889.86,662.5 1889.86,1033.27 2025,1168.41 2025,1375 2056.3,1406.3 T1.1
  Bottom Layer w50: L1.2 1659.4,892.96 C4.1@1889.86,662.5 ; C4.1 1916.25,623.61 R1.2 1916.25,452.5 R2.2
  Bottom Layer w70: R5.2 2025,1115.55 R4.2 2075,1400.79 T1.1
NetC2_2: C2.2 R9.2 | length 110.8
  Bottom Layer w70: R9.2 2219.59,1168.83 C2.2
NetC4_2: C4.2 C8.1 R7.1 R11.2 | length 907.2
  Top Layer w100: C4.2@2185.14,662.5 2332.78,514.86 2653.89,514.86
  Bottom Layer w50: C4.2@2185.14,662.5 2185.14,570.14 R7.1 R11.2@2391.25,537.5
NetC5_1: C5.1 L2.4 R6.1 RV1.2 | length 807.5
  Top Layer w50: RV1.2@800.84,308.61 R6.1 C5.1 982.82,487.5 1070.32,575 1244.68,575 L2.4
NetC5_2: C5.2 L2.1 RV1.1 TP2.1 | length 1692
  Top Layer w50: TP2.1 56.25,156.25 131.25,81.25 612.5,81.25 724.16,192.91 RV1.1 1311.81,192.91 L2.1 ; 1179.68,200.74 C5.2
NetC6_1: C6.1 D3.1 L1.1 | length 1061.6
  Bottom Layer w50: L1.1 1612.5,618.75 2025,206.25 C6.1 2219.64,266.49 D3.1@2302.51,266.49
NetC6_2: C6.2 D3.4 L3.1 | length 479.7
  Bottom Layer w50: D3.4@2459.99,266.49 2492.86,266.49 C6.2 2907.04,206.25 L3.1
NetC7_1: C7.1 D3.3 L2.3 | length 1051.5
  Top Layer w50: L2.3 1625.3,454.38 C7.1 1985.93,93.75 v3(2456.25,93.75)
  Bottom Layer w50: v3(2456.25,93.75) 2459.99,90.01 D3.3
NetC7_2: C7.2 D3.2 L2.2 | length 725
  Top Layer w50: L2.2 1703.74,76.57 C7.2
  Bottom Layer w50: C7.2 1843.06,39.76 D3.2
NetC9_1: C9.1 C11.1 D5.2 U1.2 U1.3 | length 518.3
  Top Layer w40: v2(2650,2475) D5.2 2651.97,2525 2712.5,2525 2750,2487.5 C9.1
  Bottom Layer w25: C11.1@2578.63,2566.13 U1.3 U1.2
  Bottom Layer w40: C11.1 2575,2500 2600,2475 v2(2650,2475)
NetC10_1: C10.1 R13.2 U1.5 | length 136.4
  Bottom Layer w25: R13.2@2653.43,2818.06 U1.5 C10.1@2725.87,2754.13
NetC13_1: C13.1 C14.1 R10.1 R15.1 U2.2 | length 1403
  Top Layer w50: C13.1@2758.18,1078.75 R15.1 cw(c2887.5,1072.5) 2893.75,1072.5 v1(2893.75,581.25)
  Bottom Layer w25: 2850,600 U2.2
  Bottom Layer w50: R10.1 2812.5,437.5 2893.75,518.75 v1(2893.75,581.25) 2868.75,606.25 2868.75,610.23
NetC15_1: C15.1 R19.1 U2.4 | length 174.2
  Bottom Layer w25: C15.1 2737.25,850.25 2783.37,804.13 U2.4
  Bottom Layer w30: R19.1 2725.25,880.76 C15.1
NetD1_1: D1.1 D1.3 T1.11 | length 402.3
  Top Layer w70: T1.11 2325,2194.68 2325,2275 2385.24,2335.24 D1.1@2385.24,2391.14 ; D1.1 D1.3
NetD4_1: D4.1 R4.1 R5.1 R9.1 | length 455.8
  Bottom Layer w70: R5.1 1975,984.45 R4.1 R9.1 2325.69,984.45 D4.1
NetD4_2: D4.2 Q1.4 T1.3 | length 526.4
  Top Layer w70: Q1.4@2276.57,1160.43 T1.3
  Bottom Layer w70: T1.3 2293.7,1406.3 2350,1350 D4.2
NetD5_1: D5.1 T1.10 | length 363.8
  Top Layer w40: T1.10 2424.02,2224.02 2475,2275 2587.5,2275 2650,2337.5 D5.1
NetD6_1: D6.1 R15.2 | length 118.7
  Top Layer w50: v2(2825,1162.5) R15.2@2883.75,1162.5
  Bottom Layer w50: D6.1@2765.01,1162.5 v2(2825,1162.5)
NetD6_2: D6.2 R16.2 T1.5 | length 803.5
  Bottom Layer w30: R16.2 2993.75,1177.51
  Bottom Layer w50: T1.5 2571.46,1378.54 2618.75,1331.25 2962.5,1331.25 2993.75,1300 2993.75,1177.51 2984.99,1168.75 D6.2
NetD7_1: D7.1 D8.2 | length 132.6
  Bottom Layer w30: D7.1 2840.26,972.24 2868.75,943.75 D8.2
NetD7_3: D7.3 R16.1 R18.1 | length 169.9
  Bottom Layer w30: D7.3 2934.74,1021.51 2969,987.25 R16.1 R18.1
NetQ1_1: Q1.1 R17.2 | length 435.6
  Top Layer w30: v1(2481.25,975) 2481.25,1007.63 Q1.1
  Bottom Layer w40: v1(2481.25,975) 2481.25,787.5 2568.75,700 R17.2
NetQ1_3: Q1.3 R19.2 R22.2 | length 432.4
  Top Layer w30: v1(2575,1156.25) 2575,1227.26
  Top Layer w70: 2575,1227.26 R22.2@2625.24,1227.26
  Bottom Layer w30: v1(2575,1156.25) 2575,937.5 2587.5,925 R19.2
NetR1_1: R1.1 R7.2 | length 76.2
  Bottom Layer w50: R1.1 R7.2
NetR2_1: R2.1 R8.2 | length 82.5
  Bottom Layer w50: R2.1 R8.2
NetR6_2: R6.2 TP1.1 | length 709.2
  Top Layer w50: TP1.1 56.25,475 143.75,562.5 599.16,562.5 R6.2
NetR8_1: R8.1 R10.2 | length 82.5
  Bottom Layer w50: R8.1 R10.2@2256.25,437.5
NetR11_1: R11.1 R12.2 | length 76.2
  Bottom Layer w50: R11.1 R12.2@2393.75,691.25
NetR13_1: R13.1 R14.2 U1.4 | length 127.3
  Bottom Layer w25: R14.2 U1.4@2576.27,2756.5 ; U1.4 R13.1@2578.63,2820.13
NetR17_1: R17.1 U2.3 | length 124.7
  Bottom Layer w25: R17.1@2687.88,695.87 U2.3
NetR18_2: R18.2 R20.2 U2.6 | length 153.5
  Bottom Layer w25: U2.6 2910.38,804.13 2919,812.75 R20.2 2993.5,856.25 R18.2
NetR21_2: R21.2 U2.1 | length 51.1
  Bottom Layer w25: U2.1 2935.14,695.87 R21.2
PGND: C8.2 C12.2 C13.2 C14.2 C15.2 D8.1 L3.2 R12.1 R20.1 R21.1 R22.1 T1.4 U2.5 | length 3635.3
  Top Layer w30: v2(2393.75,818.75) C8.2@2685.14,818.75
  Top Layer w50: R22.1@2637.5,1135 2637.5,872.95 2693.75,816.7 C8.2 ; C13.2 2756.25,1246.9 2762.5,1253.15 ; L3.2 2981.25,367.96 2981.25,1231.25 2959.35,1253.15 C12.2
  Top Layer w70: C8.2 2693.75,675 2800,568.75 2800,437.5 2912.5,325 L3.2
  Bottom Layer w25: 2675,1253.15 2675,1081.25 2791.78,964.47 D8.1 2800.25,935.29 C15.2 2825,868.75 2837.5,856.25 R20.1 2850,850.25 U2.5 2850,750 R21.1@2931,750 ; R21.1 2968.5,756.5 ; C14.2 2981.25,637.5 2981.25,743.75 2968.5,756.5 ; 2981.25,750 2974.75,756.5 2968.5,756.5
  Bottom Layer w30: R12.1@2393.75,771.25 v2(2393.75,818.75)
  Bottom Layer w50: T1.4 2475,1404.72 2475,1356.25 2578.1,1253.15 2675,1253.15 2762.5,1253.15
  other v1: 2775,750
pads on no net: D7.2 T1.2 T1.6 T1.7 T1.9 T1.12 T1.14

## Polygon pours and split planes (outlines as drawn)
NetD4_2 on Top Layer "Top Layer-No Net 3" (solid, remove dead copper, pour order 22): 2243.75,1393.75 2243.75,1368.75 cw(c2212.5,1368.75) 2212.5,1337.5 2168.75,1337.5 ccw(c2168.75,1293.75) 2125,1293.75 2125,1137.5 cw(c2075,1137.5) 2075,1087.5 ccw(c2075,1068.75) 2056.25,1068.75 2056.25,918.75 ccw(c2081.25,918.75) 2081.25,893.75 2356.25,893.75 ccw(c2356.25,912.5) 2375,912.5 2375,1318.75 ccw(c2350,1318.75) 2350,1343.75 cw(c2350,1381.25) 2312.5,1381.25
PGND on Top Layer "Top Layer-No Net 4" (solid, remove dead copper, pour order 18): 2460.86,1403.61 cw(c2498.36,1403.61) 2498.36,1441.11 2717.11,1441.11 cw(c2717.11,1397.36) 2760.86,1397.36 2760.86,1322.36 ccw(c2804.61,1322.36) 2804.61,1278.61 2821.59,1278.61 cw(c2821.59,1230.81) 2869.4,1230.81 2869.4,393.4 cw(c2817.11,393.4) 2817.11,341.11 2510.86,341.11 cw(c2510.86,391.11) 2460.86,391.11
NetC1_1 on Top Layer "Top Layer-No Net" (solid, pour order 0): 1975,2862.5 2603.54,2862.5 2612.5,2853.54 2612.5,2560 2565,2512.5 2287.5,2512.5 2287.5,2523.13 2185.63,2625 1975,2625
GND on Top Layer "Top Layer-No Net 1" (solid, pour order 2): 1975,2587.5 2175,2587.5 2262.5,2500 2262.5,2237.5 1975,2237.5
NetC1_1 on Top Layer "Top Layer-No Net 2" (solid, pour order 4): 2587.5,2862.5 2787.5,2862.5 2787.5,2575 2589.41,2575
PGND on Bottom Layer "Bottom Layer-No Net 1" (solid, remove dead copper, pour order 20): 2431.25,1431.25 cw(c2455.32,1431.25) 2455.32,1455.32 2675.93,1455.32 cw(c2675.93,1418.75) 2712.5,1418.75 2712.5,1300 ccw(c2731.25,1300) 2731.25,1281.25 2806.25,1281.25 cw(c2806.25,1237.5) 2850,1237.5 ccw(c2887.5,1237.5) 2887.5,1200 3006.25,1200 cw(c3006.25,1181.25) 3025,1181.25 3025,900 cw(c2993.75,900) 2993.75,868.75 2456.25,868.75 cw(c2456.25,893.75) 2431.25,893.75
PGND on Bottom Layer "Bottom Layer-No Net 2" (solid, remove dead copper, pour order 16): 2756.25,868.75 cw(c2774.95,868.75) 2774.95,887.45 2997.34,887.45 cw(c2997.34,862.5) 3022.29,862.5 3022.29,441.04 cw(c2993.75,441.04) 2993.75,412.5 2781.25,412.5 cw(c2781.25,437.5) 2756.25,437.5
GND on Bottom Layer "Bottom Layer-No Net" (solid, pour order 6): 1975,2862.5 1975,2175 2786.21,2175 2787.5,2176.29 2787.5,2862.5

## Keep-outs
Keep-Out Layer:
  text ".Layer_Name" at 577,-858.49 h60

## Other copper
Top Layer:
  text ".Layer_Name" at 577,-858.49 h60
Bottom Layer:
  text ".Layer_Name" at 577,-858.49 h60

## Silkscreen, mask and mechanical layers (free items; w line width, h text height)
Top Overlay:
  circle w10: c551.18,433.07 r39.37
  circle w10: c196.85,196.85 r39.37
  text "PMP30428_RevA" at 1518.75,1087.5 h40
  text ".Layer_Name" at 743.75,-843.75 h40
Bottom Overlay:
  text ".Layer_Name" at 577,-858.49 h40
Top Paste:
  text ".Layer_Name" at 577,-858.49 h60
Bottom Paste:
  text ".Layer_Name" at 577,-858.49 h60
Top Solder:
  text ".Layer_Name" at 577,-858.49 h60
  text ".Layer_Name" at 577,-858.49 h60
Bottom Solder:
  text ".Layer_Name" at 577,-858.49 h60
Drill Guide:
  text ".Layer_Name" at 577,-858.49 h60
M1 Board Outline:
  the board outline again, w10
  text ".Layer_Name" at 577,-858.49 h60
M2 Board Dimensions:
  rectangle: 125,-400 500,-275
  rectangle: 0,-275 125,-150
  lines w7: 0,-275 1000,-275 ; 0,-150 0,-400 1000,-400 1000,-150 ; 125,-400 125,-150 ; 250,-400 250,-150 ; 500,-400 500,-150 ; 750,-400 750,-150
  text ".Layer_Name" at 577,-858.49 h60
M3 3D STEP Top:
  text ".Layer_Name" at 577,-858.49 h60
M4 3D STEP Bottom:
  text ".Layer_Name" at 577,-858.49 h60
M5 Assembly Top:
  lines w10: -292,-930.17 6308,-930.17 ; -292,-726.83 6310,-726.83 ; -292,-523.5 -292,-1133.5 3713,-1133.5 6310,-1133.5 6310,-523.5 -291.5,-523.5 -291.5,-1133.5 1284,-1133.5 ; 2173,-1133.5 2173,-523.5 ; 3440,-726.83 3440,-523.5 ; 4280,-726.83 4280,-523.5 ; 4902,-1140 4902,-937.17
  text "PCB VIEWED FROM TOP SIDE" at -228.5,-655.67 h60
  text "BOARD #:" at 2248,-655.67 h60
  text ".PRJ_Number" at 2793.5,-655.67 h60
  text "REV:" at 3638,-655.67 h60
  text ".PCB_Rev" at 3929.5,-655.67 h60
  text "SVN REV:" at 4476,-655.67 h60
  text ".VersionControl_RevNumber" at 4982,-655.67 h60
  text "TID #:" at 2248,-859 h60
  text ".TID" at 2793.5,-859 h60
  text "PLOT NAME =" at -228.5,-1064.34 h60
  text ".plot_File_Name" at 577,-1064.34 h60
  text "GENERATED    :" at 2250,-1064.34 h60
  text ".Print_Date" at 3119.5,-1064.34 h60
  text ".Print_Time" at 3848.5,-1064.34 h60
  text "TEXAS INSTRUMENTS" at 5113,-1064.34 h60
M6 Assembly Bottom:
  lines w10: -292.5,-727.33 6309.5,-727.33 ; -290.5,-930.67 6309.5,-930.67 ; 1115.5,-1140.5 1115.5,-937.67 ; 1737.5,-727.33 1737.5,-524 ; 2577.5,-727.33 2577.5,-524 ; 3844.5,-1134 3844.5,-524 ; 4733.5,-1134 6309,-1134 6309,-524 -292.5,-524 -292.5,-1134 2304.5,-1134 6309.5,-1134 6309.5,-524
  text ".VersionControl_RevNumber" at 1035.5,-656.17 h60
  text "SVN REV:" at 1541.5,-656.17 h60
  text ".PCB_Rev" at 2088,-656.17 h60
  text "REV:" at 2379.5,-656.17 h60
  text ".PRJ_Number" at 3224,-656.17 h60
  text "BOARD #:" at 3769.5,-656.17 h60
  text "PCB VIEWED FROM BOTTOM SIDE" at 6246,-656.17 h60
  text ".TID" at 3224,-859.5 h60
  text "TID #:" at 3769.5,-859.5 h60
  text "TEXAS INSTRUMENTS" at 904.5,-1064.84 h60
  text ".Print_Time" at 2169,-1064.84 h60
  text ".Print_Date" at 2898,-1064.84 h60
  text "GENERATED    :" at 3767.5,-1064.84 h60
  text ".plot_File_Name" at 5440.5,-1064.84 h60
  text "PLOT NAME =" at 6246,-1064.84 h60
M9 Title Sheet:
  drawing of 57 lines, arcs and shapes, not listed
  text "1" at 739.84,8036.5 h70
  text "2" at 3235.5,8036.5 h70
  text "3" at 5724.84,8036.5 h70
  text "4" at 8231.51,8036.5 h70
  text "5" at 10730.5,8036.5 h70
  text "6" at 13235.5,8036.5 h70
  text "A" at -416.5,6893.5 h70
  text "A" at 14383.5,6893.5 h70
  text "B" at -416.5,4513.5 h70
  text "B" at 14383.5,4513.5 h70
  text "C" at -416.5,2138.5 h70
  text "C" at 14383.5,2138.5 h70
  text "PROJECT TITLE:" at 11343.5,277.5 h45
  text ".PRJ_Title" at 11393.5,144.17 h70
  text "DESIGNED FOR:" at 11343.5,-23.5 h45
  text ".PRJ_Customer" at 11393.5,-163.5 h70
  text "D" at -416.5,-231.5 h70
  text "D" at 14383.5,-231.5 h70
  text "FILE NAME:" at 11343.5,-323.5 h45
  text ".PCB_File_Name_No_Path" at 11393.5,-443.5 h70
  text "Texas Instruments (TI) and/or its licensors do not warrant the accuracy or completeness of this specification" at 6374,-605.34 h45
  text "ENGINEER:" at 11343.5,-613.5 h45
  text "LAYOUT BY:" at 12848.5,-613.5 h45
  text "or any information contained therein. TI and/or its licensors do not warrant that this design will meet" at 6329.01,-718 h45
  text ".PRJ_Engineer" at 11393.5,-768.49 h70
  text ".PCB_Layout" at 12899,-768.49 h70
  text "the specifications, will be suitable for your application or fit for any particular purpose, or will operate in" at 6329.01,-830.67 h45
  text ".Layer_Name" at 577,-858.49 h60
  text "ALTIUM DESIGNER VERSION:" at 12848.5,-923.5 h45
  text "an implementation. TI and/or its licensors do not warrant that the design is production worthy. You should" at 6329.01,-943.33 h45
  text "completely validate and test your design implementation to confirm the system functionality for your application." at 6374,-1056 h45
  text ".print_Scale" at 11393.5,-1056.83 h70
  text ".Application_BuildNumber" at 12899,-1056.83 h70
  text "1" at 739.84,-1263.5 h70
  text "2" at 3235.5,-1263.5 h70
  text "3" at 5724.84,-1263.5 h70
  text "4" at 8231.51,-1263.5 h70
  text "5" at 10730.5,-1263.5 h70
  text "6" at 13235.5,-1263.5 h70
M10 Fab Notes:
  lines w20: 11304,871 14295,871 14295,6451.24
  text ".Layer_Name" at 577,-858.49 h60
M11 Gerber Information:
  lines w10: -292,-930.17 6308,-930.17 ; -292,-726.83 6310,-726.83 ; -292,-523.5 -292,-1133.5 3713,-1133.5 6310,-1133.5 6310,-523.5 -291.5,-523.5 -291.5,-1133.5 1284,-1133.5 ; 2173,-1133.5 2173,-523.5 ; 3440,-726.83 3440,-523.5 ; 4280,-726.83 4280,-523.5 ; 4902,-1140 4902,-937.17
  text "ALL ARTWORK VIEWED FROM TOP SIDE" at -228.5,-655.67 h60
  text "BOARD #:" at 2248,-655.67 h60
  text ".PRJ_Number" at 2793.5,-655.67 h60
  text "REV:" at 3638,-655.67 h60
  text ".PCB_Rev" at 3929.5,-655.67 h60
  text "SVN REV:" at 4476,-655.67 h60
  text ".VersionControl_RevNumber" at 4982,-655.67 h60
  text "LAYER NAME =" at -228.5,-858.49 h60
  text "TID #:" at 2248,-859 h60
  text ".TID" at 2793.5,-859 h60
  text "PLOT NAME =" at -228.5,-1064.34 h60
  text ".plot_File_Name" at 577,-1064.34 h60
  text "GENERATED    :" at 2250,-1064.34 h60
  text ".Print_Date" at 3119.5,-1064.34 h60
  text ".Print_Time" at 3848.5,-1064.34 h60
  text "TEXAS INSTRUMENTS" at 5113,-1064.34 h60
M12 Stackup:
  text ".Layer_Name" at 577,-858.49 h60
M13 Component Bodies Top:
  text ".Layer_Name" at 577,-858.49 h60
M14 Component Bodies Bottom:
  text ".Layer_Name" at 577,-858.49 h60
M15 Courtyards Top:
  text ".Layer_Name" at 577,-858.49 h60
M16 Courtyards Bottom:
  text ".Layer_Name" at 577,-858.49 h60
Drill Drawing:
  text ".Layer_Name" at 577,-858.49 h60
M17 Embedded Cavity:
  text ".Layer_Name" at 577,-858.49 h60
M18 Embedded Assembly:
  text ".Layer_Name" at 577,-858.49 h60
M19 Embedded Keepout:
  circle w10: c551.18,433.07 r39.37
  text ".Layer_Name" at 577,-858.49 h60

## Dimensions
0,-400 to 1000,-400 on M2 Board Dimensions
